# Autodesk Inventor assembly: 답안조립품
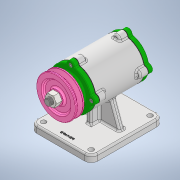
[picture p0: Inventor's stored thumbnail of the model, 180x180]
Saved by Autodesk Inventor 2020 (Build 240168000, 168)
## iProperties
Created: 2022-11
Part Number: 답안조립품
Document SubType Name: Assembly
Designer: owner
Author: owner
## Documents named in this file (12)
- C:\Users\owner\Desktop\721108V1001\답안조립품.iam
- C:\Users\owner\Desktop\721108V1001\본체.ipt
- C:\Users\owner\Desktop\721108V1001\V-벨트풀리.ipt
- C:\Users\owner\Desktop\721108V1001\개스킷.ipt
- C:\Users\owner\Desktop\721108V1001\너트 M12 x 1.25.ipt
- C:\Users\owner\Desktop\721108V1001\뒤커버.ipt
- C:\Users\owner\Desktop\721108V1001\베어링 6204.ipt
- C:\Users\owner\Desktop\721108V1001\볼트 M4 x 12.ipt
- C:\Users\owner\Desktop\721108V1001\앞커버.ipt
- C:\Users\owner\Desktop\721108V1001\오일 실.ipt
- C:\Users\owner\Desktop\721108V1001\축.ipt
- C:\Users\owner\Desktop\721108V1001\키 4 x 4.ipt
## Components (7 placed, 6 different names)
1. V-벨트풀리:1 — 각도:1
2. 개스킷:1
3. KS B 1012 클래스 1 일반 - 미터 M12x1.25:1 — 각도:1
4. KS B 2023 6204 - 20 x 47 x 14:1
5. KS B 2804 D D - 20 32 8:1
6. KS B 1311 (I) 4 x 4 x 12:1
7. 개스킷:2
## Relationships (1: Angle 1)
- 각도:1 [Angle]: V-벨트풀리:1 ↔ KS B 1012 클래스 1 일반 - 미터 M12x1.25:1
